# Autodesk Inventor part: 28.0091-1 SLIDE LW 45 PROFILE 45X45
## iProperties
Created: 2007-06
Part Number: 28.0091-1 SLIDE LW 45 PROFILE 45X45
Material: Aluminum-6061
Document SubType Name: Modeling
Designer: Andy Moles
Mass: 394.262 g
Surface Area: 934.127 cm^2
Volume: 145.484 cm^3
Density: 2.71 g/cm^3
Author: Andy Moles
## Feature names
1. Extrusion1
2. Hole1
